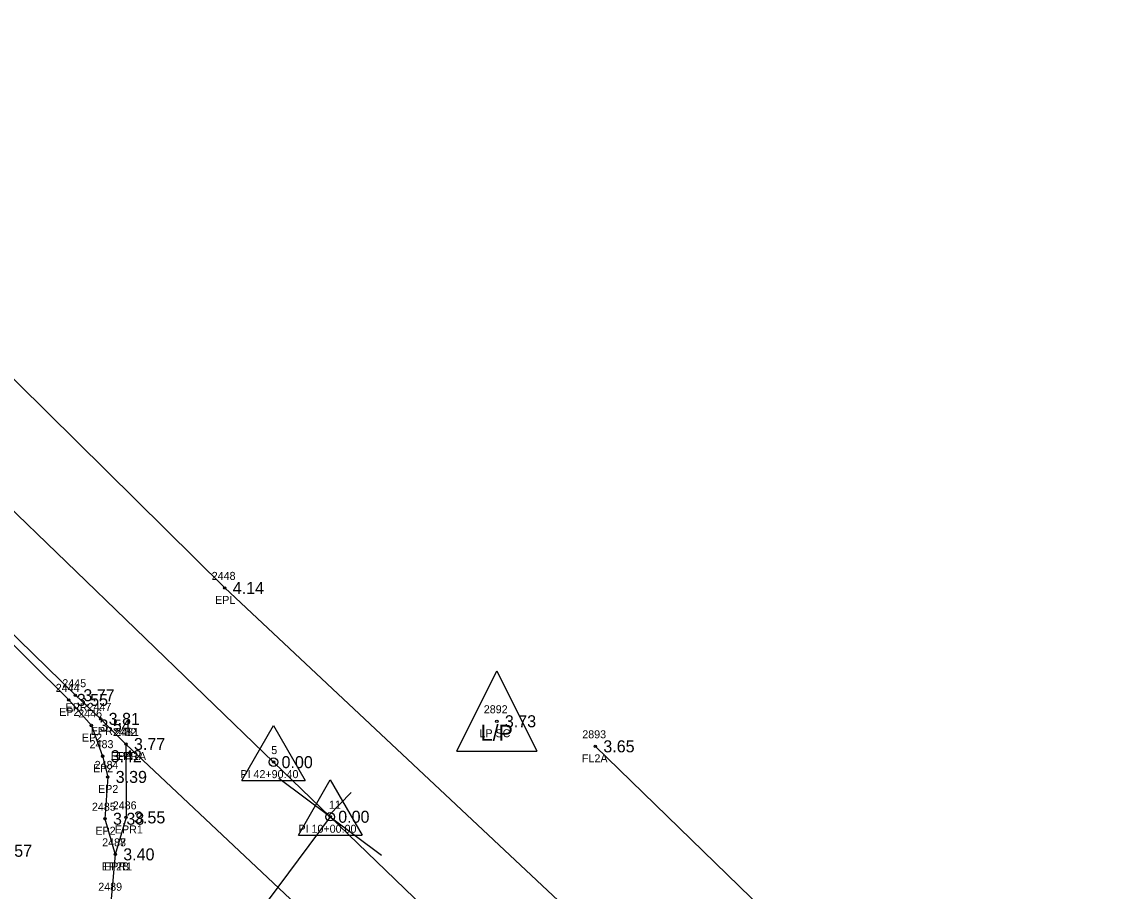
# Model space of a CAD drawing. Extents: x 2608598 to 2610682, y 641451 to 643526.
# Drawn here: x 2610061 to 2610198.2, y 642124.7 to 642233.2 of the extents above; entities that cross this region are included whole.
import ezdxf

# ---------------------------------------------------------------- set-up
doc = ezdxf.new("R2010")
doc.units = 0
for name, color, linetype in [('RD_EX_Fence_Other', 7, 'Continuous'), ('RD_EX_Fence_Other_txCode', 7, 'Continuous'), ('RD_EX_Road', 7, 'Continuous'), ('RD_EX_Road_txCode', 7, 'Continuous'), ('RD_EX_TX_Fence_Other_ELEV', 7, 'Continuous'), ('RD_EX_TX_H2O_ELEV', 7, 'Continuous'), ('RD_EX_TX_Road_ELEV', 7, 'Continuous'), ('RD_EX_TX_UT_ELEV', 7, 'Continuous'), ('RD_EX_UT', 7, 'Continuous'), ('RD_EX_UT_txCode', 7, 'Continuous'), ('RD_HC_Cl', 7, 'Continuous'), ('RD_HC_Data', 7, 'Continuous'), ('RD_HC_Data_Tic', 7, 'Continuous'), ('RD_HC_Survey_ELEV', 7, 'Continuous'), ('RD_HC_txCode', 7, 'Continuous'), ('RD_SMD_Locator', 7, 'Continuous')]:
    doc.layers.add(name, color=color, linetype=linetype)

msp = doc.modelspace()

# ---------------------------------------------------------------- linework, layer by layer
at = {"layer": 'RD_EX_Fence_Other'}
msp.add_lwpolyline([(2610132.58, 642142.76), (2610200.01, 642077.23), (2610202.79, 642080.05), (2610213.52, 642069.87), (2610210.47, 642066.29), (2610214.96, 642062.54)], dxfattribs=at)
at = {"layer": 'RD_EX_Road'}
for points in [[(2609576.61, 642656.06), (2609590.88, 642642.24), (2609605.19, 642628.78), (2609627.58, 642607.09), (2609646.03, 642589.11), (2609702.18, 642534.04), (2609780.35, 642458.95), (2609858.79, 642382.83), (2609938.32, 642306.42), (2610008.62, 642239.32), (2610086.3, 642162.54), (2610164.18, 642089.49), (2610189.2, 642065.46), (2610214.78, 642040.19), (2610225.86, 642030.16), (2610226.32, 642028.39), (2610235.43, 642019.75), (2610260.23, 641995.63), (2610272.39, 641983.25)], [(2609979.13, 642234.19), (2609992.4, 642221.66), (2610004.86, 642210.01), (2610027, 642188.8), (2610067.64, 642149.14), (2610070.8, 642146.19), (2610073.96, 642143.05), (2610116.51, 642103.01), (2610119.68, 642100.06), (2610135.09, 642085.92), (2610148.33, 642073.03), (2610165.14, 642055.61), (2610179.59, 642041.57), (2610196.49, 642024.71), (2610209.86, 642011.42), (2610228.39, 641994.06), (2610252.93, 641970.08), (2610256.35, 641966.74)], [(2609991.14, 642222.22), (2610004.6, 642209.66), (2610026.66, 642188.37), (2610066.82, 642148.56), (2610069.65, 642145.36), (2610071.05, 642141.53), (2610071.68, 642138.94), (2610071.34, 642133.72), (2610072.62, 642129.27)], [(2610073.96, 642143.05), (2610073.97, 642133.89), (2610072.62, 642129.27), (2610072.13, 642123.73), (2610071.19, 642117.59), (2610042.94, 642077.42), (2610042.98, 642077.08), (2610020.81, 642047.62), (2610010.68, 642034.57), (2609995.36, 642013.51), (2609993.98, 642012.16), (2609992.65, 642010.59), (2609982.73, 641996.33), (2609971.73, 641982.02), (2609971.56, 641981.9), (2609966, 641974.62)]]:
    msp.add_lwpolyline(points, dxfattribs=at)
at = {"layer": 'RD_EX_UT'}
for p, q in [((2610115.28, 642142.17), (2610120.28, 642152.17)), ((2610120.28, 642152.17), (2610125.28, 642142.17)), ((2610115.28, 642142.17), (2610125.28, 642142.17))]:
    msp.add_line(p, q, dxfattribs=at)
at = {"layer": 'RD_HC_Cl'}
for p, q in [((2608814.81, 643373.73), (2610092.39, 642140.79)), ((2610092.39, 642140.79), (2610263.67, 641975.86)), ((2610099.47, 642133.97), (2609975.32, 641967.39))]:
    msp.add_line(p, q, dxfattribs=at)
at = {"layer": 'RD_HC_Data'}
for p, q in [((2610088.42, 642138.49), (2610092.4, 642145.37)), ((2610092.4, 642145.37), (2610096.36, 642138.49)), ((2610088.42, 642138.49), (2610096.36, 642138.49)), ((2610095.5, 642131.68), (2610099.48, 642138.56)), ((2610099.48, 642138.56), (2610103.44, 642131.68)), ((2610095.5, 642131.68), (2610103.44, 642131.68))]:
    msp.add_line(p, q, dxfattribs=at)
for centre in [(2610092.39, 642140.79), (2610099.47, 642133.97)]:
    msp.add_circle(centre, 0.529, dxfattribs=at)
at = {"layer": 'RD_HC_Data_Tic'}
for p, q in [((2610099.47, 642133.97), (2610093.06, 642138.75)), ((2610099.31, 642134.13), (2610102.08, 642137.01)), ((2610099.47, 642133.97), (2610105.89, 642129.19))]:
    msp.add_line(p, q, dxfattribs=at)
at = {"layer": 'RD_SMD_Locator'}
for centre in [(2610086.3, 642162.54), (2610067.64, 642149.14), (2610066.82, 642148.56), (2610070.8, 642146.19), (2610120.28, 642145.89), (2610069.65, 642145.36), (2610073.96, 642143.05), (2610073.96, 642143.05), (2610132.58, 642142.76), (2610071.05, 642141.53), (2610092.39, 642140.79), (2610071.68, 642138.94), (2610071.34, 642133.72), (2610073.97, 642133.89), (2610099.47, 642133.97), (2610072.62, 642129.27), (2610072.62, 642129.27)]:
    msp.add_circle(centre, 0.15, dxfattribs=at)

# ---------------------------------------------------------------- texts
at = {"layer": 'RD_EX_Fence_Other_txCode'}
for s, p in [('2893', (2610130.95, 642143.76)), ('FL2A', (2610130.91, 642140.76))]:
    msp.add_text(s, height=1, dxfattribs=at).set_placement(p)
at = {"layer": 'RD_EX_Road_txCode'}
for s, p in [('2448', (2610084.67, 642163.54)), ('EPL', (2610085.09, 642160.54)), ('2444', (2610065.19, 642149.56)), ('2445', (2610066.01, 642150.14)), ('EP2', (2610065.62, 642146.56)), ('EPR', (2610066.41, 642147.14)), ('2446', (2610068, 642146.36)), ('2447', (2610069.17, 642147.19)), ('EPR', (2610069.57, 642144.19)), ('2482', (2610072.33, 642144.05)), ('2481', (2610072.61, 642144.05)), ('EP2', (2610068.45, 642143.36)), ('2483', (2610069.42, 642142.53)), ('EPR1A', (2610072.08, 642141.05)), ('EPR', (2610072.73, 642141.05)), ('EP2', (2610069.84, 642139.53)), ('2484', (2610070.05, 642139.94)), ('EP2', (2610070.47, 642136.94)), ('2485', (2610069.71, 642134.72)), ('2486', (2610072.31, 642134.89)), ('EP2', (2610070.14, 642131.72)), ('EPR1', (2610072.57, 642131.89)), ('2487', (2610070.99, 642130.27)), ('2488', (2610070.99, 642130.27)), ('EP2B', (2610070.94, 642127.27)), ('EPR1', (2610071.23, 642127.27)), ('2489', (2610070.5, 642124.73))]:
    msp.add_text(s, height=1, dxfattribs=at).set_placement(p)
at = {"layer": 'RD_EX_TX_Fence_Other_ELEV'}
msp.add_text('3.65', height=1.5, dxfattribs=at).set_placement((2610133.58, 642142.01))
at = {"layer": 'RD_EX_TX_H2O_ELEV'}
msp.add_text('2.57', height=1.5, dxfattribs=at).set_placement((2610058.33, 642128.97))
at = {"layer": 'RD_EX_TX_Road_ELEV'}
for s, p in [('4.14', (2610087.3, 642161.79)), ('3.55', (2610067.82, 642147.81)), ('3.77', (2610068.64, 642148.39)), ('3.54', (2610070.65, 642144.61)), ('3.81', (2610071.8, 642145.44)), ('3.77', (2610074.96, 642142.3)), ('3.77', (2610074.96, 642142.3)), ('3.42', (2610072.05, 642140.78)), ('3.39', (2610072.68, 642138.19)), ('3.38', (2610072.34, 642132.97)), ('3.55', (2610074.97, 642133.14)), ('3.40', (2610073.62, 642128.52)), ('3.40', (2610073.62, 642128.52))]:
    msp.add_text(s, height=1.5, dxfattribs=at).set_placement(p)
at = {"layer": 'RD_EX_TX_UT_ELEV'}
msp.add_text('3.73', height=1.5, dxfattribs=at).set_placement((2610121.28, 642145.14))
at = {"layer": 'RD_EX_UT'}
msp.add_text('L/P', height=2, dxfattribs=at).set_placement((2610118.27, 642143.45))
at = {"layer": 'RD_EX_UT_txCode'}
for s, p in [('2892', (2610118.65, 642146.89)), ('LP SC', (2610118.11, 642143.89))]:
    msp.add_text(s, height=1, dxfattribs=at).set_placement(p)
at = {"layer": 'RD_HC_Survey_ELEV'}
for p in [(2610093.39, 642140.04), (2610100.47, 642133.22)]:
    msp.add_text('0.00', height=1.5, dxfattribs=at).set_placement(p)
at = {"layer": 'RD_HC_txCode'}
for s, p in [('5', (2610092.11, 642141.79)), ('PI 42+90.40', (2610088.25, 642138.79)), ('11', (2610099.31, 642134.97)), ('PI 10+00.00', (2610095.5, 642131.97))]:
    msp.add_text(s, height=1, dxfattribs=at).set_placement(p)

doc.saveas('drawing.dxf')
